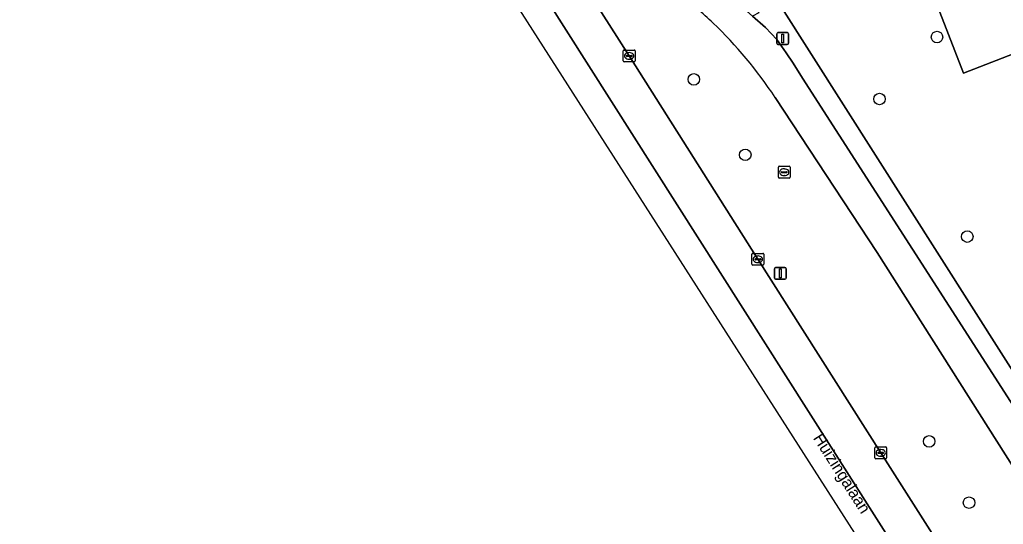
# Model space of a CAD drawing. Extents: x 159680 to 160786, y 387323 to 388340.
# Drawn here: x 159909.6 to 159993.2, y 387475 to 387517.9 of the extents above; entities that cross this region are included whole.
import ezdxf

# ---------------------------------------------------------------- set-up
doc = ezdxf.new("R2010")
doc.units = 0
for name, color, linetype in [('IMGEO_Berm_groen', 7, 'Continuous'), ('IMGEO_Boom', 7, 'Continuous'), ('IMGEO_Fietspad_gesloten', 7, 'Continuous'), ('IMGEO_Groenvoorziening', 7, 'Continuous'), ('IMGEO_Kolk', 7, 'Continuous'), ('IMGEO_Lichtmast', 7, 'Continuous'), ('IMGEO_Openbare_ruimte_label', 7, 'Continuous'), ('IMGEO_OVBaan_gesloten', 7, 'Continuous'), ('IMGEO_Rijbaan_regionaal_gesloten', 7, 'Continuous'), ('IMGEO_Rioolput', 7, 'Continuous'), ('IMGEO_Voetpad_open', 7, 'Continuous')]:
    doc.layers.add(name, color=color, linetype=linetype)

msp = doc.modelspace()

# ---------------------------------------------------------------- linework, layer by layer
at = {"layer": 'IMGEO_Berm_groen'}
for points in [[(159950.281, 387532.241), (159950.928, 387531.209), (159961.373, 387514.792), (159972.307, 387497.514), (159982.75, 387481.068), (159993.719, 387463.849), (159994.343, 387462.819)], [(160005.194, 387462.233), (159982.432, 387498.094), (159973.775, 387511.273)]]:
    msp.add_lwpolyline(points, dxfattribs=at)
for centre, radius, start, end in [((159943.038, 387490.988), 36.821, 46.25459, 51.9214), ((159942.892, 387490.828), 37.037, 33.50446, 46.26179)]:
    msp.add_arc(centre, radius, start, end, dxfattribs=at)
at = {"layer": 'IMGEO_Boom'}
for centre in [(159987.531, 387516.398), (159966.862, 387512.801), (159982.647, 387511.134), (159971.237, 387506.388), (159990.105, 387499.443), (159986.859, 387482.042), (159990.254, 387476.833)]:
    msp.add_circle(centre, 0.489, dxfattribs=at)
at = {"layer": 'IMGEO_Fietspad_gesloten'}
for points in [[(160078.431, 387352.066), (160075.581, 387356.553), (160061.437, 387378.989), (160060.642, 387380.243), (160057.964, 387384.46), (160057.586, 387385.068), (160057.126, 387385.767), (160026.112, 387434.619), (159994.797, 387483.84), (159976.098, 387512.903), (159975.302, 387514.189), (159974.711, 387515.066), (159973.915, 387516.188), (159972.956, 387517.208), (159971.859, 387518.161), (159969.874, 387519.968), (159965.379, 387524.114), (159961.252, 387528.133), (159955.875, 387535.138), (159951.54, 387542.782), (159948.393, 387551.166), (159948.152, 387552.118)], [(159973.775, 387511.273), (159982.432, 387498.094), (160005.194, 387462.233), (160015.444, 387446.083), (160022.875, 387434.376), (160026.822, 387428.159), (160038.072, 387410.44), (160050.495, 387390.874), (160054.843, 387384.025), (160073.194, 387354.946), (160076.577, 387349.719), (160077.187, 387348.931), (160079.636, 387350.623)]]:
    msp.add_lwpolyline(points, dxfattribs=at)
for centre, radius, start, end in [((159943.038, 387490.988), 36.821, 46.25459, 51.9214), ((159942.892, 387490.828), 37.037, 33.50446, 46.26179)]:
    msp.add_arc(centre, radius, start, end, dxfattribs=at)
at = {"layer": 'IMGEO_Groenvoorziening'}
msp.add_lwpolyline([(160019.905, 387500), (160017.909, 387504.817), (160025.253, 387507.75), (160012.723, 387539.639), (160000, 387534.671), (159983.944, 387528.402), (159989.768, 387513.317), (159997.738, 387516.43), (160000, 387510.573), (160004.081, 387500), (160009.681, 387485.486), (160000, 387481.351), (159998.615, 387480.704), (160026.502, 387436.824), (160058.389, 387386.599), (160060.082, 387383.969), (160060.586, 387384.345), (160070.282, 387393.417)], dxfattribs=at)
msp.add_lwpolyline([(160000, 387510.573), (159997.738, 387516.43), (159989.768, 387513.317), (159983.944, 387528.402), (159971.413, 387523.508), (159998.615, 387480.704), (160000, 387481.351), (160009.681, 387485.486), (160004.081, 387500)], close=True, dxfattribs=at)
at = {"layer": 'IMGEO_Kolk'}
for p, q in [((159960.947, 387515.292), (159961.799, 387515.292)), ((159960.872, 387514.366), (159960.872, 387515.218)), ((159961.131, 387514.786), (159961.131, 387514.798)), ((159961.569, 387514.749), (159961.171, 387514.749)), ((159961.174, 387514.835), (159961.572, 387514.835)), ((159961.383, 387514.512), (159961.358, 387514.512)), ((159961.36, 387515.072), (159961.385, 387515.072)), ((159961.615, 387514.798), (159961.615, 387514.786)), ((159961.873, 387515.218), (159961.873, 387514.366)), ((159961.799, 387514.292), (159960.947, 387514.292)), ((159971.806, 387497.088), (159971.806, 387497.94)), ((159971.881, 387498.014), (159972.733, 387498.014)), ((159972.294, 387497.794), (159972.319, 387497.794)), ((159972.807, 387497.94), (159972.807, 387497.088)), ((159972.733, 387497.014), (159971.881, 387497.014)), ((159972.065, 387497.508), (159972.065, 387497.52)), ((159972.503, 387497.471), (159972.105, 387497.471)), ((159972.108, 387497.557), (159972.506, 387497.557)), ((159972.317, 387497.234), (159972.292, 387497.234)), ((159972.549, 387497.52), (159972.549, 387497.508)), ((159982.249, 387480.642), (159982.249, 387481.494)), ((159982.324, 387481.568), (159983.176, 387481.568)), ((159982.508, 387481.062), (159982.508, 387481.074)), ((159982.946, 387481.025), (159982.548, 387481.025)), ((159982.551, 387481.111), (159982.949, 387481.111)), ((159982.737, 387481.348), (159982.762, 387481.348)), ((159982.992, 387481.074), (159982.992, 387481.062)), ((159983.25, 387481.494), (159983.25, 387480.642)), ((159983.176, 387480.568), (159982.324, 387480.568)), ((159982.76, 387480.788), (159982.735, 387480.788))]:
    msp.add_line(p, q, dxfattribs=at)
for points in [[(159960.947, 387515.292), (159961.799, 387515.292)], [(159960.872, 387514.366), (159960.872, 387515.218)], [(159961.873, 387515.218), (159961.873, 387514.366)], [(159961.799, 387514.292), (159960.947, 387514.292)], [(159971.806, 387497.088), (159971.806, 387497.94)], [(159971.881, 387498.014), (159972.733, 387498.014)], [(159972.807, 387497.94), (159972.807, 387497.088)], [(159972.733, 387497.014), (159971.881, 387497.014)], [(159982.249, 387480.642), (159982.249, 387481.494)], [(159982.324, 387481.568), (159983.176, 387481.568)], [(159983.25, 387481.494), (159983.25, 387480.642)], [(159983.176, 387480.568), (159982.324, 387480.568)]]:
    msp.add_lwpolyline(points, dxfattribs=at)
for centre, radius, start, end in [((159960.949, 387515.216), 0.0765, 91.55205, 178.44795), ((159960.949, 387515.216), 0.0765, 91.55205, 178.44795), ((159961.797, 387515.216), 0.0765, 1.55205, 88.44795), ((159961.797, 387515.216), 0.0765, 1.55205, 88.44795), ((159961.171, 387514.795), 0.0403, 85.87752, 175.75265), ((159961.168, 387514.785), 0.0366, 178.93798, 274.71019), ((159961.572, 387514.792), 0.043, 264.86636, 352.45326), ((159961.576, 387514.797), 0.0386, 1.73085, 96.63898), ((159960.949, 387514.368), 0.0765, 181.55205, 268.44795), ((159960.949, 387514.368), 0.0765, 181.55205, 268.44795), ((159961.797, 387514.368), 0.0765, 271.55205, 358.44795), ((159961.797, 387514.368), 0.0765, 271.55205, 358.44795), ((159971.883, 387497.938), 0.0765, 91.55205, 178.44795), ((159971.883, 387497.938), 0.0765, 91.55205, 178.44795), ((159972.731, 387497.938), 0.0765, 1.55205, 88.44795), ((159972.731, 387497.938), 0.0765, 1.55205, 88.44795), ((159971.883, 387497.09), 0.0765, 181.55205, 268.44795), ((159971.883, 387497.09), 0.0765, 181.55205, 268.44795), ((159972.105, 387497.517), 0.0403, 85.87752, 175.75265), ((159972.102, 387497.507), 0.0366, 178.93798, 274.71019), ((159972.506, 387497.514), 0.043, 264.86636, 352.45326), ((159972.51, 387497.519), 0.0386, 1.73085, 96.63898), ((159972.731, 387497.09), 0.0765, 271.55205, 358.44795), ((159972.731, 387497.09), 0.0765, 271.55205, 358.44795), ((159982.326, 387481.492), 0.0765, 91.55205, 178.44795), ((159982.326, 387481.492), 0.0765, 91.55205, 178.44795), ((159982.548, 387481.071), 0.0403, 85.87752, 175.75265), ((159982.545, 387481.061), 0.0366, 178.93798, 274.71019), ((159982.949, 387481.068), 0.043, 264.86636, 352.45326), ((159982.953, 387481.073), 0.0386, 1.73085, 96.63898), ((159983.174, 387481.492), 0.0765, 1.55205, 88.44795), ((159983.174, 387481.492), 0.0765, 1.55205, 88.44795), ((159982.326, 387480.644), 0.0765, 181.55205, 268.44795), ((159982.326, 387480.644), 0.0765, 181.55205, 268.44795), ((159983.174, 387480.644), 0.0765, 271.55205, 358.44795), ((159983.174, 387480.644), 0.0765, 271.55205, 358.44795)]:
    msp.add_arc(centre, radius, start, end, dxfattribs=at)
for centre, major_axis, ratio, start_param, end_param in [((159961.359, 387514.792), (-0.387, 0.002), 0.722429, 4.712389, 7.853982), ((159961.384, 387514.792), (-0.39, 0.002), 0.717154, 1.570796, 4.712389), ((159972.293, 387497.514), (-0.387, 0.002), 0.722429, 4.712389, 7.853982), ((159972.318, 387497.514), (-0.39, 0.002), 0.717154, 1.570796, 4.712389), ((159982.736, 387481.068), (-0.387, 0.002), 0.722429, 4.712389, 7.853982), ((159982.761, 387481.068), (-0.39, 0.002), 0.717154, 1.570796, 4.712389)]:
    msp.add_ellipse(centre, major_axis=major_axis, ratio=ratio, start_param=start_param, end_param=end_param, dxfattribs=at)
at = {"layer": 'IMGEO_Lichtmast'}
for p, q in [((159973.916, 387515.871), (159973.916, 387516.671)), ((159973.916, 387516.671), (159973.916, 387515.871)), ((159974.016, 387516.771), (159974.806, 387516.771)), ((159974.806, 387516.771), (159974.016, 387516.771)), ((159974.906, 387516.671), (159974.906, 387515.871)), ((159974.906, 387515.871), (159974.906, 387516.671)), ((159974.806, 387515.771), (159974.016, 387515.771)), ((159974.016, 387515.771), (159974.806, 387515.771)), ((159973.719, 387495.914), (159973.719, 387496.714)), ((159973.719, 387496.714), (159973.719, 387495.914)), ((159973.819, 387496.814), (159974.609, 387496.814)), ((159974.609, 387496.814), (159973.819, 387496.814)), ((159974.709, 387496.714), (159974.709, 387495.914)), ((159974.709, 387495.914), (159974.709, 387496.714)), ((159974.609, 387495.814), (159973.819, 387495.814)), ((159973.819, 387495.814), (159974.609, 387495.814))]:
    msp.add_line(p, q, dxfattribs=at)
for points in [[(159974.336, 387516.646), (159974.486, 387516.646), (159974.486, 387515.896), (159974.336, 387515.896), (159974.336, 387516.646)], [(159974.139, 387496.689), (159974.289, 387496.689), (159974.289, 387495.939), (159974.139, 387495.939), (159974.139, 387496.689)]]:
    msp.add_lwpolyline(points, dxfattribs=at)
for centre, start, end in [((159974.016, 387516.671), 90, 180), ((159974.016, 387516.671), 90, 180), ((159974.806, 387516.671), 0, 90), ((159974.806, 387516.671), 360, 90), ((159974.016, 387515.871), 180, 270), ((159974.016, 387515.871), 180, 270), ((159974.806, 387515.871), 270, 0), ((159974.806, 387515.871), 270, 0), ((159973.819, 387496.714), 90, 180), ((159973.819, 387496.714), 90, 180), ((159974.609, 387496.714), 0, 90), ((159974.609, 387496.714), 360, 90), ((159973.819, 387495.914), 180, 270), ((159973.819, 387495.914), 180, 270), ((159974.609, 387495.914), 270, 0), ((159974.609, 387495.914), 270, 0)]:
    msp.add_arc(centre, 0.1, start, end, dxfattribs=at)
at = {"layer": 'IMGEO_OVBaan_gesloten'}
for points in [[(159858.121, 387669.257), (159855.36, 387672.605), (159852.108, 387676.163), (159883.278, 387626.179), (159920.558, 387567.925), (159984.842, 387467.474), (160065.277, 387340.998)], [(160065.277, 387340.998), (160066.652, 387341.76), (160065.959, 387342.848), (160051.196, 387366.436), (160037.469, 387388.37), (160035.007, 387392.266), (160025.491, 387407.303), (159999.061, 387448.992), (159999.203, 387449.069), (159985.84, 387470.05), (159937.564, 387546.059), (159937.458, 387545.975), (159928.344, 387560.272), (159926.726, 387562.813), (159919.709, 387573.899), (159910.99, 387587.597), (159899.844, 387605.107), (159900.012, 387605.234), (159869.099, 387654.066)]]:
    msp.add_lwpolyline(points, dxfattribs=at)
at = {"layer": 'IMGEO_Rijbaan_regionaal_gesloten'}
for points in [[(159911.794, 387592.201), (159913.655, 387589.274), (159929.395, 387564.514), (159929.83, 387563.83), (159930.599, 387562.585), (159930.974, 387561.949), (159928.344, 387560.272), (159937.458, 387545.975), (159937.564, 387546.059), (159985.84, 387470.05), (159999.203, 387449.069), (159999.616, 387449.328)], [(159994.343, 387462.819), (159993.719, 387463.849), (159982.75, 387481.068), (159972.307, 387497.514), (159961.373, 387514.792), (159950.928, 387531.209), (159950.281, 387532.241)]]:
    msp.add_lwpolyline(points, dxfattribs=at)
at = {"layer": 'IMGEO_Rioolput'}
for p, q in [((159974.05, 387504.49), (159974.05, 387505.342)), ((159974.125, 387505.416), (159974.977, 387505.416)), ((159974.538, 387505.196), (159974.563, 387505.196)), ((159975.051, 387505.342), (159975.051, 387504.49)), ((159974.977, 387504.416), (159974.125, 387504.416)), ((159974.309, 387504.91), (159974.309, 387504.922)), ((159974.747, 387504.873), (159974.349, 387504.873)), ((159974.352, 387504.959), (159974.75, 387504.959)), ((159974.561, 387504.636), (159974.536, 387504.636)), ((159974.793, 387504.922), (159974.793, 387504.91))]:
    msp.add_line(p, q, dxfattribs=at)
for points in [[(159974.05, 387504.49), (159974.05, 387505.342)], [(159974.125, 387505.416), (159974.977, 387505.416)], [(159975.051, 387505.342), (159975.051, 387504.49)], [(159974.977, 387504.416), (159974.125, 387504.416)]]:
    msp.add_lwpolyline(points, dxfattribs=at)
for centre, radius, start, end in [((159974.127, 387505.34), 0.0765, 91.55205, 178.44795), ((159974.127, 387505.34), 0.0765, 91.55205, 178.44795), ((159974.975, 387505.34), 0.0765, 1.55205, 88.44795), ((159974.975, 387505.34), 0.0765, 1.55205, 88.44795), ((159974.127, 387504.492), 0.0765, 181.55205, 268.44795), ((159974.127, 387504.492), 0.0765, 181.55205, 268.44795), ((159974.349, 387504.919), 0.0403, 85.87752, 175.75265), ((159974.346, 387504.909), 0.0366, 178.93798, 274.71019), ((159974.75, 387504.916), 0.043, 264.86636, 352.45326), ((159974.754, 387504.921), 0.0386, 1.73085, 96.63898), ((159974.975, 387504.492), 0.0765, 271.55205, 358.44795), ((159974.975, 387504.492), 0.0765, 271.55205, 358.44795)]:
    msp.add_arc(centre, radius, start, end, dxfattribs=at)
for centre, major_axis, ratio, start_param, end_param in [((159974.537, 387504.916), (-0.387, 0.002), 0.722429, 4.712389, 7.853982), ((159974.562, 387504.916), (-0.39, 0.002), 0.717154, 1.570796, 4.712389)]:
    msp.add_ellipse(centre, major_axis=major_axis, ratio=ratio, start_param=start_param, end_param=end_param, dxfattribs=at)
at = {"layer": 'IMGEO_Voetpad_open'}
for points in [[(160060.082, 387383.969), (160058.389, 387386.599), (160026.502, 387436.824), (159998.615, 387480.704), (159971.413, 387523.508), (159970.076, 387525.611), (159946.727, 387562.351)], [(159947.491, 387554.288), (159948.2, 387554.802), (159954.609, 387545.512), (159961.607, 387534.821), (159966.402, 387527.68), (159969.177, 387523.497), (159972.38, 387518.458), (159971.859, 387518.161), (159972.956, 387517.208), (159973.915, 387516.188), (159974.711, 387515.066), (159975.302, 387514.189), (159976.098, 387512.903), (159994.797, 387483.84), (160026.112, 387434.619), (160057.126, 387385.767), (160057.586, 387385.068), (160057.964, 387384.46)]]:
    msp.add_lwpolyline(points, dxfattribs=at)

# ---------------------------------------------------------------- texts
at = {"layer": 'IMGEO_Openbare_ruimte_label'}
msp.add_text('Huizingalaan', height=1, rotation=302.4668, dxfattribs=at).set_placement((159976.962, 387482.323))

doc.saveas('drawing.dxf')
